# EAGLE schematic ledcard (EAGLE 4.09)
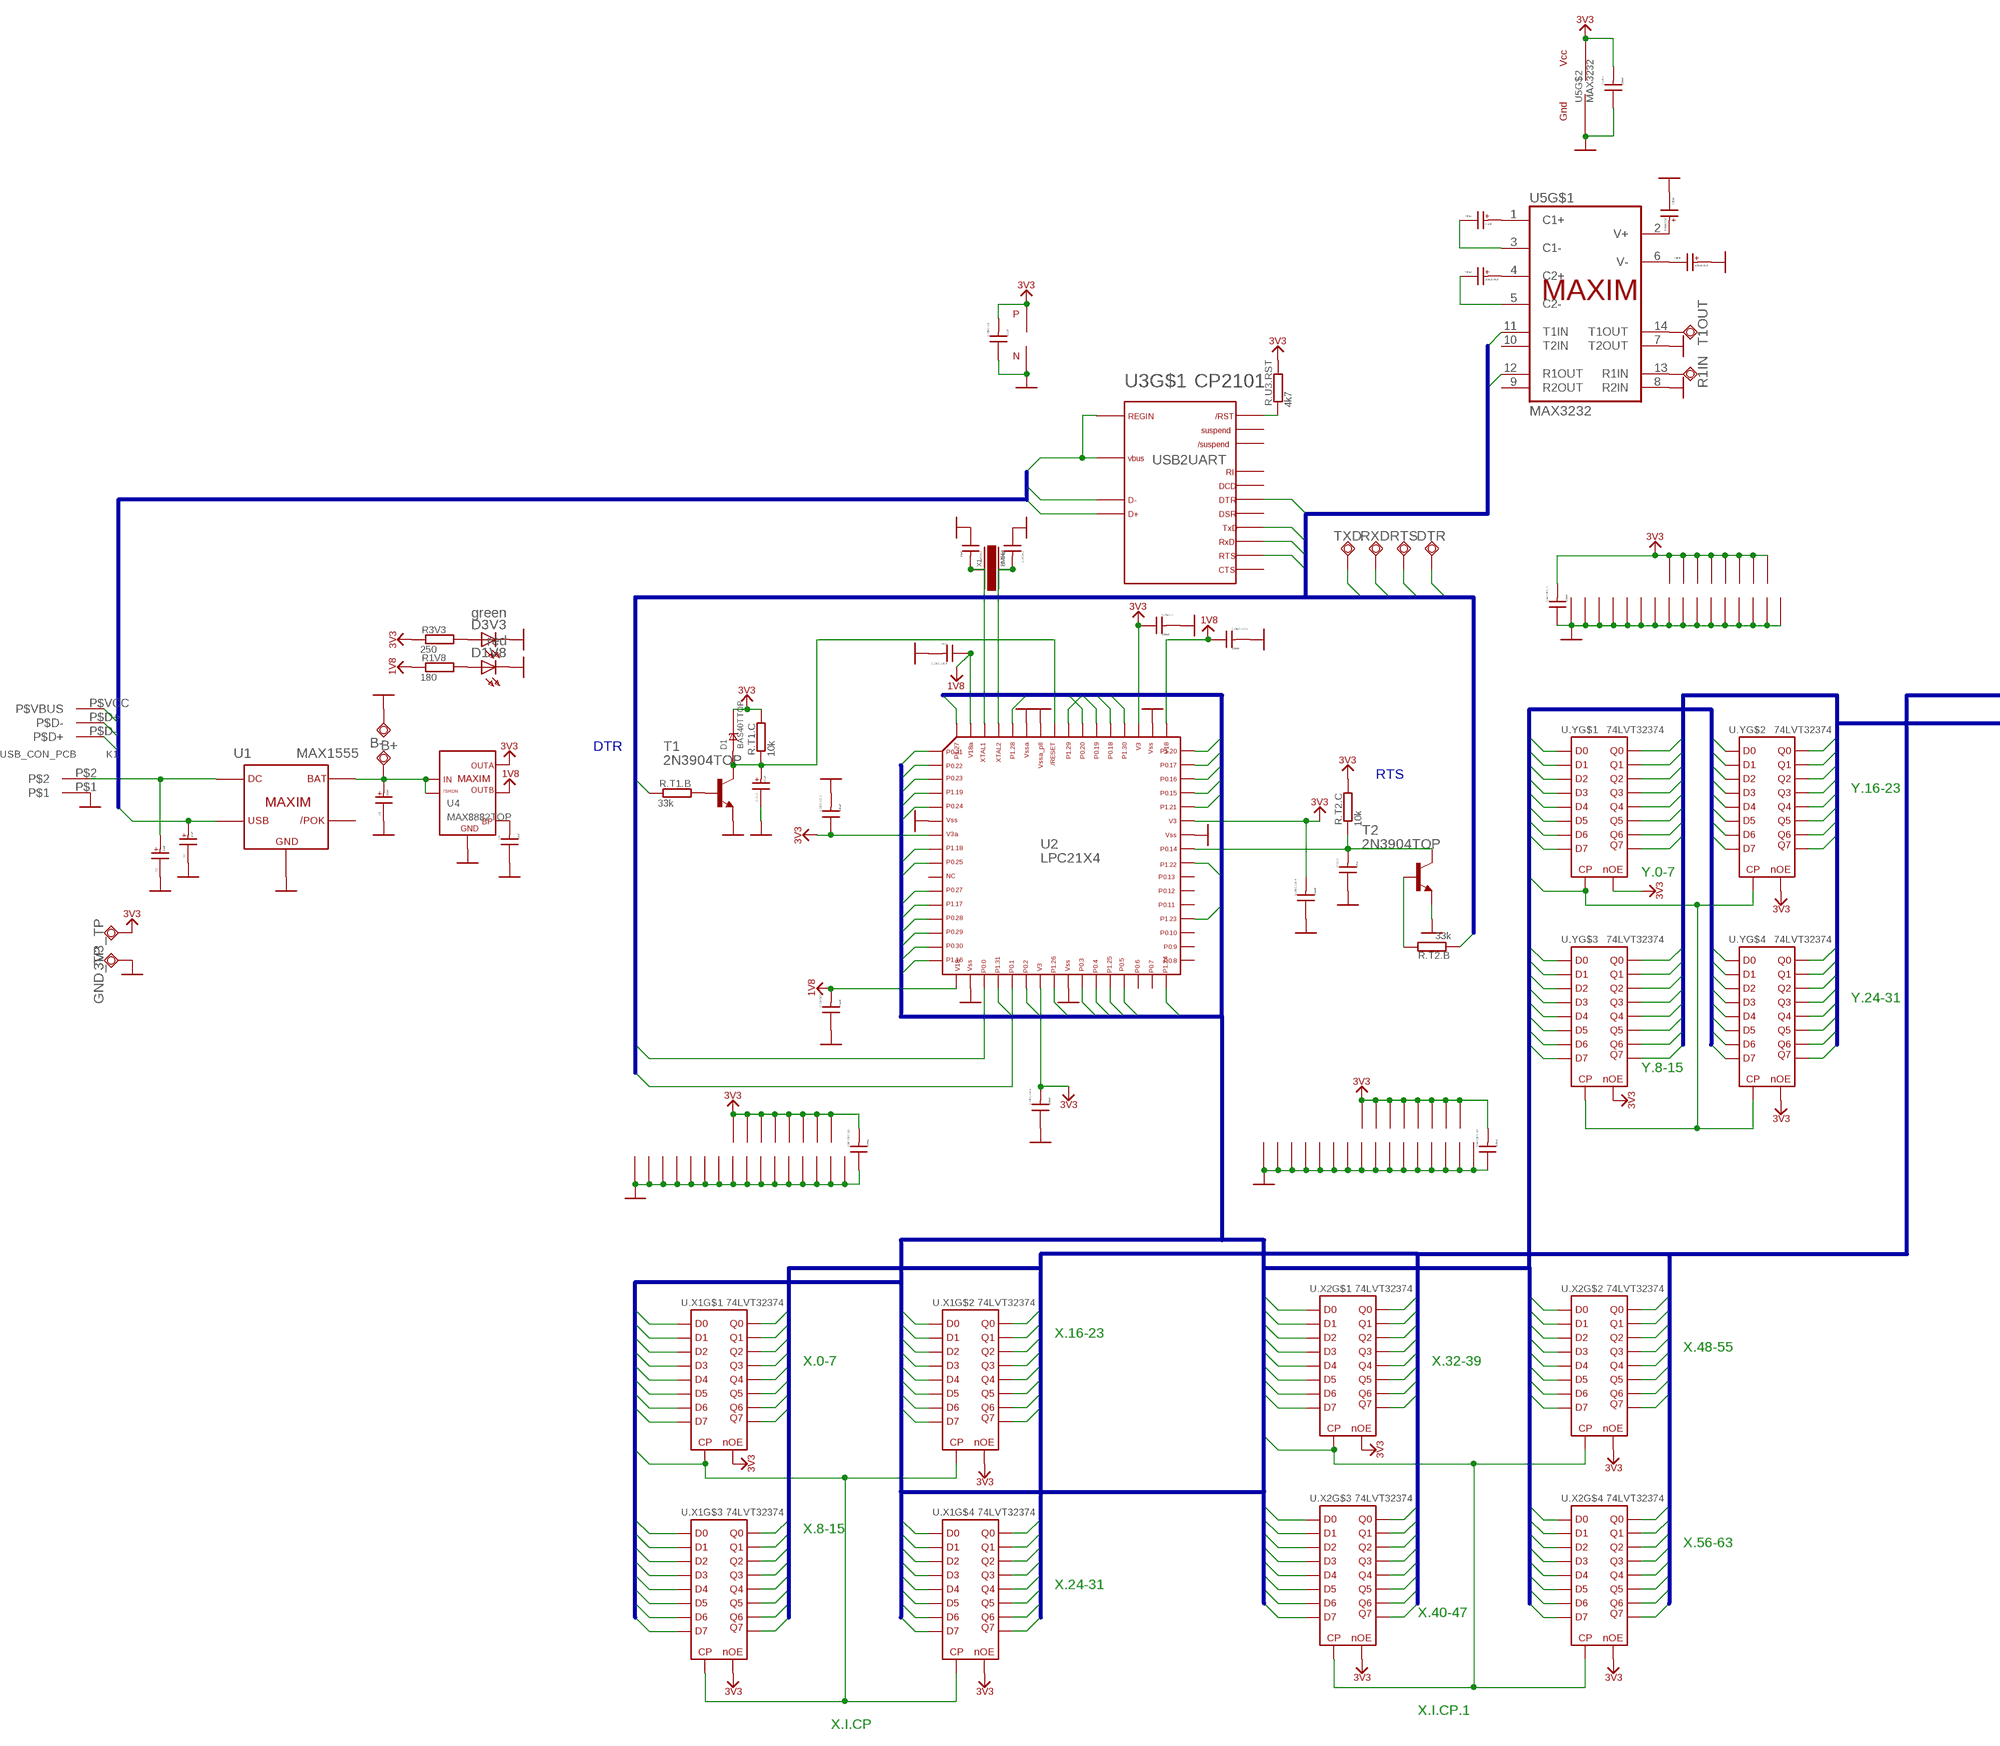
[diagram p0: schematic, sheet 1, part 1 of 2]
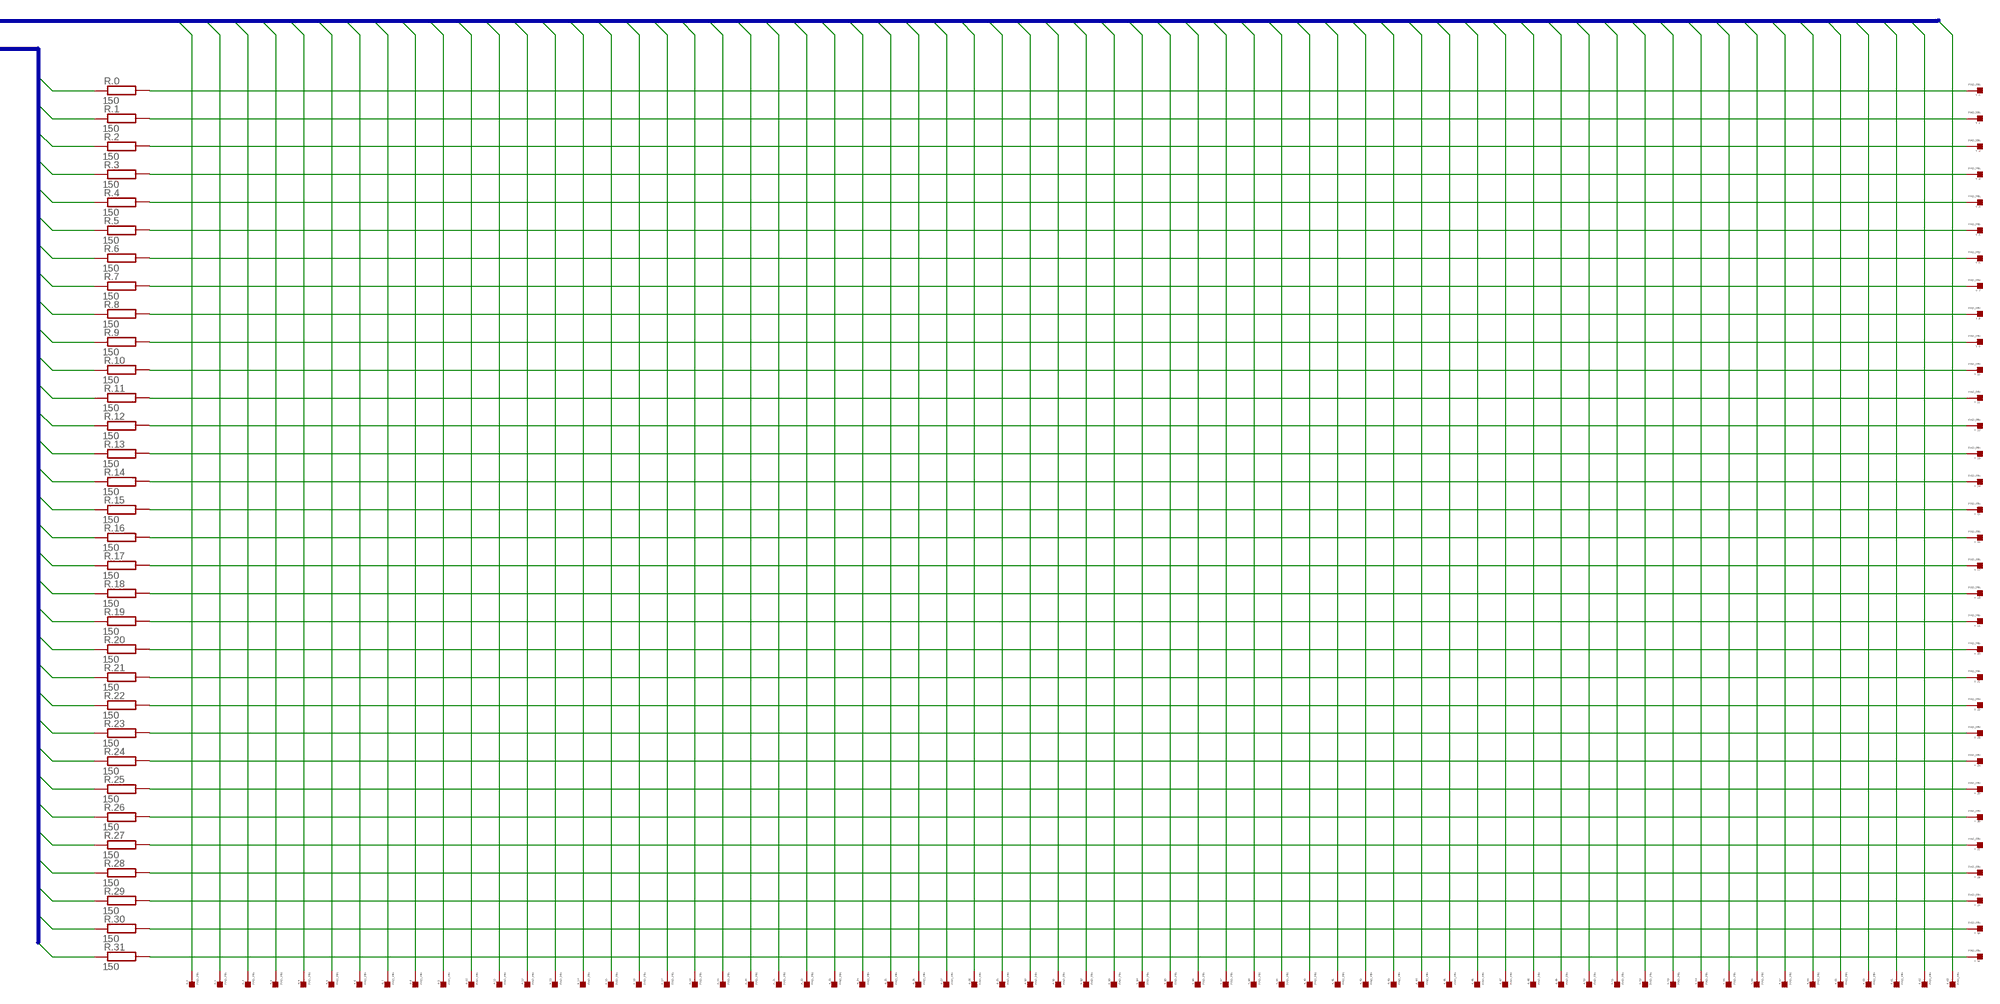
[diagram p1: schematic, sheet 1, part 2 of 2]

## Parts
3V3_TP  B2,54  [B2,54]
B+  B2,54  [B2,54]
B-  B2,54  [B2,54]
C1  10uF  CAP_A  [CAP_A]
C2  10uF  CAP_A  [CAP_A]
C3  10uF  CAP_A  [CAP_A]
C4  10uF  CAP_CERAMIC  [CAP_CERAMIC]
C.DEC.1  100nF  CAP_CERAMIC  [CAP_CERAMIC]
C.DEC.U2.1  100nF  CAP_CERAMIC  [CAP_CERAMIC]
C.DEC.U2.3  100nF  CAP_CERAMIC  [CAP_CERAMIC]
C.DEC.U2.5  100nF  CAP_CERAMIC  [CAP_CERAMIC]
C.DEC.U2.6  100n  CAP_CERAMIC  [CAP_CERAMIC]
C.DEC.U3  0.1uF  CAP_CERAMIC  [CAP_CERAMIC]
C.T1.C  10uF  CAP_A  [CAP_A]
C.T2.C  100n  CAP_CERAMIC  [CAP_CERAMIC]
C.U2.DEC.2  100nF  CAP_CERAMIC  [CAP_CERAMIC]
C.U5.1  100nF  CAP_CERAMIC  [CAP_CERAMIC]
C.XTAL1  22pF  CAP_CERAMIC  [CAP_CERAMIC]
C.XTAL2  22pF  CAP_CERAMIC  [CAP_CERAMIC]
CAP.DEC.X1  100Nf  CAP_CERAMIC  [CAP_CERAMIC]
CAP.DEC.X2  100nF  CAP_CERAMIC  [CAP_CERAMIC]
CAP.DEC.Y  100nF  CAP_CERAMIC  [CAP_CERAMIC]
D1  BAS40TTOP  [SOT23]
D1V8  red  LED0603_TOP  [LED_0603]
D3V3  green  LED0603_TOP  [LED_0603]
D.DEC.U2.4  100nF  CAP_CERAMIC  [CAP_CERAMIC]
DTR  B2,54  [B2,54]
GND_TP  B2,54  [B2,54]
K1  USB_CON_PCB  [USB_CON]
R1IN  B2,54  [B2,54]
R1V8  180  SMD_R  [SMDR]
R3V3  250  SMD_R  [SMDR]
R.0  150  SMD_R  [SMDR]
R.1  150  SMD_R  [SMDR]
R.2  150  SMD_R  [SMDR]
R.3  150  SMD_R  [SMDR]
R.4  150  SMD_R  [SMDR]
R.5  150  SMD_R  [SMDR]
R.6  150  SMD_R  [SMDR]
R.7  150  SMD_R  [SMDR]
R.8  150  SMD_R  [SMDR]
R.9  150  SMD_R  [SMDR]
R.10  150  SMD_R  [SMDR]
R.11  150  SMD_R  [SMDR]
R.12  150  SMD_R  [SMDR]
R.13  150  SMD_R  [SMDR]
R.14  150  SMD_R  [SMDR]
R.15  150  SMD_R  [SMDR]
R.16  150  SMD_R  [SMDR]
R.17  150  SMD_R  [SMDR]
R.18  150  SMD_R  [SMDR]
R.19  150  SMD_R  [SMDR]
R.20  150  SMD_R  [SMDR]
R.21  150  SMD_R  [SMDR]
R.22  150  SMD_R  [SMDR]
R.23  150  SMD_R  [SMDR]
R.24  150  SMD_R  [SMDR]
R.25  150  SMD_R  [SMDR]
R.26  150  SMD_R  [SMDR]
R.27  150  SMD_R  [SMDR]
R.28  150  SMD_R  [SMDR]
R.29  150  SMD_R  [SMDR]
R.30  150  SMD_R  [SMDR]
R.31  150  SMD_R  [SMDR]
R.T1.B  33k  SMD_R  [SMDR]
R.T1.C  10k  SMD_R  [SMDR]
R.T2.B  33k  SMD_R  [SMDR]
R.T2.C  10k  SMD_R  [SMDR]
R.U3.RST  4k7  SMD_R  [SMDR]
RTS  B2,54  [B2,54]
RXD  B2,54  [B2,54]
T1  2N3904TOP  [SOT23]
T1OUT  B2,54  [B2,54]
T2  2N3904TOP  [SOT23]
TXD  B2,54  [B2,54]
U1  MAX1555  [SOT23-5]
U2  LPC21X4  [TQFP64]
U3  CP2101  [MLP-28]
U4  MAX8882TOP  [SOT-23_RT6]
U5  MAX3232  [TSOP16]
U$3  PIN2  [PIN2]
U$31  0.1uF  CAP_A  [CAP_A]
U$32  470nF/TNT  CAP_A  [CAP_A]
U$33  470nF/TNT  CAP_A  [CAP_A]
U$36  470nF/TNT  CAP_A  [CAP_A]
U.X1  74LVT32374  [LFBGA96]
U.X2  74LVT32374  [LFBGA96]
U.Y  74LVT32374  [LFBGA96]
X1  8MHz  XTAL  [XTAL]
X.0  PAD_PIN  [PAD0.012]
X.1  PAD_PIN  [PAD0.012]
X.2  PAD_PIN  [PAD0.012]
X.3  PAD_PIN  [PAD0.012]
X.4  PAD_PIN  [PAD0.012]
X.5  PAD_PIN  [PAD0.012]
X.6  PAD_PIN  [PAD0.012]
X.7  PAD_PIN  [PAD0.012]
X.8  PAD_PIN  [PAD0.012]
X.9  PAD_PIN  [PAD0.012]
X.10  PAD_PIN  [PAD0.012]
X.11  PAD_PIN  [PAD0.012]
X.12  PAD_PIN  [PAD0.012]
X.13  PAD_PIN  [PAD0.012]
X.14  PAD_PIN  [PAD0.012]
X.15  PAD_PIN  [PAD0.012]
X.16  PAD_PIN  [PAD0.012]
X.17  PAD_PIN  [PAD0.012]
X.18  PAD_PIN  [PAD0.012]
X.19  PAD_PIN  [PAD0.012]
X.20  PAD_PIN  [PAD0.012]
X.21  PAD_PIN  [PAD0.012]
X.22  PAD_PIN  [PAD0.012]
X.23  PAD_PIN  [PAD0.012]
X.24  PAD_PIN  [PAD0.012]
X.25  PAD_PIN  [PAD0.012]
X.26  PAD_PIN  [PAD0.012]
X.27  PAD_PIN  [PAD0.012]
X.28  PAD_PIN  [PAD0.012]
X.29  PAD_PIN  [PAD0.012]
X.30  PAD_PIN  [PAD0.012]
X.31  PAD_PIN  [PAD0.012]
X.32  PAD_PIN  [PAD0.012]
X.33  PAD_PIN  [PAD0.012]
X.34  PAD_PIN  [PAD0.012]
X.35  PAD_PIN  [PAD0.012]
X.36  PAD_PIN  [PAD0.012]
X.37  PAD_PIN  [PAD0.012]
X.38  PAD_PIN  [PAD0.012]
X.39  PAD_PIN  [PAD0.012]
X.40  PAD_PIN  [PAD0.012]
X.41  PAD_PIN  [PAD0.012]
X.42  PAD_PIN  [PAD0.012]
X.43  PAD_PIN  [PAD0.012]
X.44  PAD_PIN  [PAD0.012]
X.45  PAD_PIN  [PAD0.012]
X.46  PAD_PIN  [PAD0.012]
X.47  PAD_PIN  [PAD0.012]
X.48  PAD_PIN  [PAD0.012]
X.49  PAD_PIN  [PAD0.012]
X.50  PAD_PIN  [PAD0.012]
X.51  PAD_PIN  [PAD0.012]
X.52  PAD_PIN  [PAD0.012]
X.53  PAD_PIN  [PAD0.012]
X.54  PAD_PIN  [PAD0.012]
X.55  PAD_PIN  [PAD0.012]
X.56  PAD_PIN  [PAD0.012]
X.57  PAD_PIN  [PAD0.012]
X.58  PAD_PIN  [PAD0.012]
X.59  PAD_PIN  [PAD0.012]
X.60  PAD_PIN  [PAD0.012]
X.61  PAD_PIN  [PAD0.012]
X.62  PAD_PIN  [PAD0.012]
X.63  PAD_PIN  [PAD0.012]
Y.0  PAD_PIN  [PAD0.012]
Y.1  PAD_PIN  [PAD0.012]
Y.2  PAD_PIN  [PAD0.012]
Y.3  PAD_PIN  [PAD0.012]
Y.4  PAD_PIN  [PAD0.012]
Y.5  PAD_PIN  [PAD0.012]
Y.6  PAD_PIN  [PAD0.012]
Y.7  PAD_PIN  [PAD0.012]
Y.8  PAD_PIN  [PAD0.012]
Y.9  PAD_PIN  [PAD0.012]
Y.10  PAD_PIN  [PAD0.012]
Y.11  PAD_PIN  [PAD0.012]
Y.12  PAD_PIN  [PAD0.012]
Y.13  PAD_PIN  [PAD0.012]
Y.14  PAD_PIN  [PAD0.012]
Y.15  PAD_PIN  [PAD0.012]
Y.16  PAD_PIN  [PAD0.012]
Y.17  PAD_PIN  [PAD0.012]
Y.18  PAD_PIN  [PAD0.012]
Y.19  PAD_PIN  [PAD0.012]
Y.20  PAD_PIN  [PAD0.012]
Y.21  PAD_PIN  [PAD0.012]
Y.22  PAD_PIN  [PAD0.012]
Y.23  PAD_PIN  [PAD0.012]
Y.24  PAD_PIN  [PAD0.012]
Y.25  PAD_PIN  [PAD0.012]
Y.26  PAD_PIN  [PAD0.012]
Y.27  PAD_PIN  [PAD0.012]
Y.28  PAD_PIN  [PAD0.012]
Y.29  PAD_PIN  [PAD0.012]
Y.30  PAD_PIN  [PAD0.012]
Y.31  PAD_PIN  [PAD0.012]

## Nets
1V8: C.DEC.U2.5.P$1 C.DEC.U2.6.P$1 C.U2.DEC.2.P$2 R1V8.P$1 U2.17 U2.49 U2.63 U4.1(P$OUT_B_1)
3V3: 3V3_TP.PP C.DEC.1.P$1 C.DEC.U2.1.P$1 C.DEC.U2.3.P$2 C.DEC.U3.P$2 C.U5.1.P$2 CAP.DEC.X1.P$2 CAP.DEC.X2.P$2 CAP.DEC.Y.P$2 D1.3(K) D.DEC.U2.4.P$2 R3V3.P$1 R.T1.C.P$2 R.T2.C.P$2 R.U3.RST.P$2 U2.7 U2.23 U2.43 U2.51 U3.P$6(P$P) U4.6(P$OUT_A_6) U5.16(VCC) U.X1.P$A3(P$NOE) U.X1.P$C3 U.X1.P$C4 U.X1.P$F3 U.X1.P$F4 U.X1.P$H3(P$NOE) U.X1.P$J3(P$NOE) U.X1.P$L3 U.X1.P$L4 U.X1.P$P3 U.X1.P$P4 U.X1.P$T3(P$NOE) U.X2.P$A3(P$NOE) U.X2.P$C3 U.X2.P$C4 U.X2.P$F3 U.X2.P$F4 U.X2.P$H3(P$NOE) U.X2.P$J3(P$NOE) U.X2.P$L3 U.X2.P$L4 U.X2.P$P3 U.X2.P$P4 U.X2.P$T3(P$NOE) U.Y.P$A3(P$NOE) U.Y.P$C3 U.Y.P$C4 U.Y.P$F3 U.Y.P$F4 U.Y.P$H3(P$NOE) U.Y.P$J3(P$NOE) U.Y.P$L3 U.Y.P$L4 U.Y.P$P3 U.Y.P$P4 U.Y.P$T3(P$NOE)
B$COM.DTR: DTR.PP R.T1.B.P$1 U3.P$28(P$DTR)
B$COM.RTS: R.T2.B.P$1 RTS.PP U3.P$9(P$RTS)
B$COM.RXD: RXD.PP U2.21 U3.P$25(P$RXD) U5.12(R1OUT)
B$COM.TXD: TXD.PP U2.19 U3.P$26(P$TXD) U5.11(T1IN)
B$I.0: U2.45 U.X1.P$A5(P$D0) U.X2.P$A5(P$D0) U.Y.P$A5(P$D0)
B$I.1: U2.46 U.X1.P$A6(P$D1) U.X2.P$A6(P$D1) U.Y.P$A6(P$D1)
B$I.2: U2.47 U.X1.P$B5(P$D2) U.X2.P$B5(P$D2) U.Y.P$B5(P$D2)
B$I.3: U2.53 U.X1.P$B6(P$D3) U.X2.P$B6(P$D3) U.Y.P$B6(P$D3)
B$I.4: U2.54 U.X1.P$C5(P$D4) U.X2.P$C5(P$D4) U.Y.P$C5(P$D4)
B$I.5: U2.55 U.X1.P$C6(P$D5) U.X2.P$C6(P$D5) U.Y.P$C6(P$D5)
B$I.6: U2.1 U.X1.P$D5(P$D6) U.X2.P$D5(P$D6) U.Y.P$D5(P$D6)
B$I.7: U2.2 U.X1.P$D6(P$D7) U.X2.P$D6(P$D7) U.Y.P$D6(P$D7)
B$I.8: U2.3 U.X1.P$J5(P$D0) U.X2.P$J5(P$D0) U.Y.P$J5(P$D0)
B$I.9: U2.5 U.X1.P$J6(P$D1) U.X2.P$J6(P$D1) U.Y.P$J6(P$D1)
B$I.10: U2.9 U.X1.P$K5(P$D2) U.X2.P$K5(P$D2) U.Y.P$K5(P$D2)
B$I.11: U2.29 U.X1.P$K6(P$D3) U.X2.P$K6(P$D3) U.Y.P$K6(P$D3)
B$I.12: U2.11 U.X1.P$L5(P$D4) U.X2.P$L5(P$D4) U.Y.P$L5(P$D4)
B$I.13: U2.13 U.X1.P$L6(P$D5) U.X2.P$L6(P$D5) U.Y.P$L6(P$D5)
B$I.14: U2.14 U.X1.P$M5(P$D6) U.X2.P$M5(P$D6) U.Y.P$M5(P$D6)
B$I.15: U2.15 U.X1.P$M6(P$D7) U.X2.P$M6(P$D7) U.Y.P$M6(P$D7)
B$I.16: U2.16 U.X1.P$E5(P$D0) U.X2.P$E5(P$D0) U.Y.P$E5(P$D0)
B$I.17: U2.12 U.X1.P$E6(P$D1) U.X2.P$E6(P$D1) U.Y.P$E6(P$D1)
B$I.18: U2.8 U.X1.P$F5(P$D2) U.X2.P$F5(P$D2) U.Y.P$F5(P$D2)
B$I.19: U2.4 U.X1.P$F6(P$D3) U.X2.P$F6(P$D3) U.Y.P$F6(P$D3)
B$I.20: U2.48 U.X1.P$G5(P$D4) U.X2.P$G5(P$D4) U.Y.P$G5(P$D4)
B$I.21: U2.44 U.X1.P$G6(P$D5) U.X2.P$G6(P$D5) U.Y.P$G6(P$D5)
B$I.22: U2.40 U.X1.P$H6(P$D6) U.X2.P$H6(P$D6) U.Y.P$H6(P$D6)
B$I.23: U2.36 U.X1.P$H5(P$D7) U.X2.P$H5(P$D7) U.Y.P$H5(P$D7)
B$I.24: U2.32 U.X1.P$N5(P$D0) U.X2.P$N5(P$D0) U.Y.P$N5(P$D0)
B$I.25: U2.28 U.X1.P$N6(P$D1) U.X2.P$N6(P$D1) U.Y.P$N6(P$D1)
B$I.26: U2.24 U.X1.P$P5(P$D2) U.X2.P$P5(P$D2) U.Y.P$P5(P$D2)
B$I.27: U2.64 U.X1.P$P6(P$D3) U.X2.P$P6(P$D3) U.Y.P$P6(P$D3)
B$I.28: U2.60 U.X1.P$R5(P$D4) U.X2.P$R5(P$D4) U.Y.P$R5(P$D4)
B$I.29: U2.56 U.X1.P$R6(P$D5) U.X2.P$R6(P$D5) U.Y.P$R6(P$D5)
B$I.30: U2.52 U.X1.P$T6(P$D6) U.X2.P$T6(P$D6) U.Y.P$T6(P$D6)
B$I.31: U2.20 U.X1.P$T5(P$D7) U.X2.P$T5(P$D7) U.Y.P$T5(P$D7)
B$USB.D+: K1.P$D-(P$D+) U3.P$4(P$D+)
B$USB.D-: K1.P$D+(P$D-) U3.P$5(P$D-)
B$USB.VBUS: C2.P K1.P$VCC(P$VBUS) U1.1(P$USB) U3.P$7(P$REGIN) U3.P$8(P$VBUS)
B$X.I.CP: U2.22 U.X1.P$A4(P$CP) U.X1.P$H4(P$CP) U.X1.P$J4(P$CP) U.X1.P$T4(P$CP)
B$X.I.CP.1: U2.26 U.X2.P$A4(P$CP) U.X2.P$H4(P$CP) U.X2.P$J4(P$CP) U.X2.P$T4(P$CP)
B$X.O.0: U.X1.P$A2(P$Q0) X.0.P$
B$X.O.1: U.X1.P$A1(P$Q1) X.1.P$
B$X.O.2: U.X1.P$B2(P$Q2) X.2.P$
B$X.O.3: U.X1.P$B1(P$Q3) X.3.P$
B$X.O.4: U.X1.P$C2(P$Q4) X.4.P$
B$X.O.5: U.X1.P$C1(P$Q5) X.5.P$
B$X.O.6: U.X1.P$D2(P$Q6) X.6.P$
B$X.O.7: U.X1.P$D1(P$Q7) X.7.P$
B$X.O.8: U.X1.P$J2(P$Q0) X.8.P$
B$X.O.9: U.X1.P$J1(P$Q1) X.9.P$
B$X.O.10: U.X1.P$K2(P$Q2) X.10.P$
B$X.O.11: U.X1.P$K1(P$Q3) X.11.P$
B$X.O.12: U.X1.P$L2(P$Q4) X.12.P$
B$X.O.13: U.X1.P$L1(P$Q5) X.13.P$
B$X.O.14: U.X1.P$M2(P$Q6) X.14.P$
B$X.O.15: U.X1.P$M1(P$Q7) X.15.P$
B$X.O.16: U.X1.P$E2(P$Q0) X.16.P$
B$X.O.17: U.X1.P$E1(P$Q1) X.17.P$
B$X.O.18: U.X1.P$F2(P$Q2) X.18.P$
B$X.O.19: U.X1.P$F1(P$Q3) X.19.P$
B$X.O.20: U.X1.P$G2(P$Q4) X.20.P$
B$X.O.21: U.X1.P$G1(P$Q5) X.21.P$
B$X.O.22: U.X1.P$H1(P$Q6) X.22.P$
B$X.O.23: U.X1.P$H2(P$Q7) X.23.P$
B$X.O.24: U.X1.P$N2(P$Q0) X.24.P$
B$X.O.25: U.X1.P$N1(P$Q1) X.25.P$
B$X.O.26: U.X1.P$P2(P$Q2) X.26.P$
B$X.O.27: U.X1.P$P1(P$Q3) X.27.P$
B$X.O.28: U.X1.P$R2(P$Q4) X.28.P$
B$X.O.29: U.X1.P$R1(P$Q5) X.29.P$
B$X.O.30: U.X1.P$T1(P$Q6) X.30.P$
B$X.O.31: U.X1.P$T2(P$Q7) X.31.P$
B$X.O.32: U.X2.P$A2(P$Q0) X.32.P$
B$X.O.33: U.X2.P$A1(P$Q1) X.33.P$
B$X.O.34: U.X2.P$B2(P$Q2) X.34.P$
B$X.O.35: U.X2.P$B1(P$Q3) X.35.P$
B$X.O.36: U.X2.P$C2(P$Q4) X.36.P$
B$X.O.37: U.X2.P$C1(P$Q5) X.37.P$
B$X.O.38: U.X2.P$D2(P$Q6) X.38.P$
B$X.O.39: U.X2.P$D1(P$Q7) X.39.P$
B$X.O.40: U.X2.P$J2(P$Q0) X.40.P$
B$X.O.41: U.X2.P$J1(P$Q1) X.41.P$
B$X.O.42: U.X2.P$K2(P$Q2) X.42.P$
B$X.O.43: U.X2.P$K1(P$Q3) X.43.P$
B$X.O.44: U.X2.P$L2(P$Q4) X.44.P$
B$X.O.45: U.X2.P$L1(P$Q5) X.45.P$
B$X.O.46: U.X2.P$M2(P$Q6) X.46.P$
B$X.O.47: U.X2.P$M1(P$Q7) X.47.P$
B$X.O.48: U.X2.P$E2(P$Q0) X.48.P$
B$X.O.49: U.X2.P$E1(P$Q1) X.49.P$
B$X.O.50: U.X2.P$F2(P$Q2) X.50.P$
B$X.O.51: U.X2.P$F1(P$Q3) X.51.P$
B$X.O.52: U.X2.P$G2(P$Q4) X.52.P$
B$X.O.53: U.X2.P$G1(P$Q5) X.53.P$
B$X.O.54: U.X2.P$H1(P$Q6) X.54.P$
B$X.O.55: U.X2.P$H2(P$Q7) X.55.P$
B$X.O.56: U.X2.P$N2(P$Q0) X.56.P$
B$X.O.57: U.X2.P$N1(P$Q1) X.57.P$
B$X.O.58: U.X2.P$P2(P$Q2) X.58.P$
B$X.O.59: U.X2.P$P1(P$Q3) X.59.P$
B$X.O.60: U.X2.P$R2(P$Q4) X.60.P$
B$X.O.61: U.X2.P$R1(P$Q5) X.61.P$
B$X.O.62: U.X2.P$T1(P$Q6) X.62.P$
B$X.O.63: U.X2.P$T2(P$Q7) X.63.P$
B$Y.I.CP: U2.27 U.Y.P$A4(P$CP) U.Y.P$H4(P$CP) U.Y.P$J4(P$CP) U.Y.P$T4(P$CP)
B$Y.O.0: R.0.P$1 U.Y.P$A2(P$Q0)
B$Y.O.1: R.1.P$1 U.Y.P$A1(P$Q1)
B$Y.O.2: R.2.P$1 U.Y.P$B2(P$Q2)
B$Y.O.3: R.3.P$1 U.Y.P$B1(P$Q3)
B$Y.O.4: R.4.P$1 U.Y.P$C2(P$Q4)
B$Y.O.5: R.5.P$1 U.Y.P$C1(P$Q5)
B$Y.O.6: R.6.P$1 U.Y.P$D2(P$Q6)
B$Y.O.7: R.7.P$1 U.Y.P$D1(P$Q7)
B$Y.O.8: R.8.P$1 U.Y.P$J2(P$Q0)
B$Y.O.9: R.9.P$1 U.Y.P$J1(P$Q1)
B$Y.O.10: R.10.P$1 U.Y.P$K2(P$Q2)
B$Y.O.11: R.11.P$1 U.Y.P$K1(P$Q3)
B$Y.O.12: R.12.P$1 U.Y.P$L2(P$Q4)
B$Y.O.13: R.13.P$1 U.Y.P$L1(P$Q5)
B$Y.O.14: R.14.P$1 U.Y.P$M2(P$Q6)
B$Y.O.15: R.15.P$1 U.Y.P$M1(P$Q7)
B$Y.O.16: R.16.P$1 U.Y.P$E2(P$Q0)
B$Y.O.17: R.17.P$1 U.Y.P$E1(P$Q1)
B$Y.O.18: R.18.P$1 U.Y.P$F2(P$Q2)
B$Y.O.19: R.19.P$1 U.Y.P$F1(P$Q3)
B$Y.O.20: R.20.P$1 U.Y.P$G2(P$Q4)
B$Y.O.21: R.21.P$1 U.Y.P$G1(P$Q5)
B$Y.O.22: R.22.P$1 U.Y.P$H1(P$Q6)
B$Y.O.23: R.23.P$1 U.Y.P$H2(P$Q7)
B$Y.O.24: R.24.P$1 U.Y.P$N2(P$Q0)
B$Y.O.25: R.25.P$1 U.Y.P$N1(P$Q1)
B$Y.O.26: R.26.P$1 U.Y.P$P2(P$Q2)
B$Y.O.27: R.27.P$1 U.Y.P$P1(P$Q3)
B$Y.O.28: R.28.P$1 U.Y.P$R2(P$Q4)
B$Y.O.29: R.29.P$1 U.Y.P$R1(P$Q5)
B$Y.O.30: R.30.P$1 U.Y.P$T1(P$Q6)
B$Y.O.31: R.31.P$1 U.Y.P$T2(P$Q7)
GND: B-.PP C1.N C2.N C3.N C4.P$1 C.DEC.1.P$2 C.DEC.U2.1.P$2 C.DEC.U2.3.P$1 C.DEC.U2.5.P$2 C.DEC.U2.6.P$2 C.DEC.U3.P$1 C.T1.C.N C.T2.C.P$1 C.U2.DEC.2.P$1 C.U5.1.P$1 C.XTAL1.P$1 C.XTAL2.P$1 CAP.DEC.X1.P$1 CAP.DEC.X2.P$1 CAP.DEC.Y.P$1 D1V8.P$K(C) D3V3.P$K(C) D.DEC.U2.4.P$1 GND_TP.PP T1.2(E) T2.2(E) U1.2(P$GND) U2.6 U2.18 U2.25 U2.42 U2.50 U2.58 U2.59 U3.P$3(P$N) U4.2(P$GND_2) U5.7(T2OUT) U5.8(R2IN) U5.15(GND) U$3.P$1 U$33.N U$36.P U.X1.P$B3 U.X1.P$B4 U.X1.P$D3 U.X1.P$D4 U.X1.P$E3 U.X1.P$E4 U.X1.P$G3 U.X1.P$G4 U.X1.P$K3 U.X1.P$K4 U.X1.P$M3 U.X1.P$M4 U.X1.P$N3 U.X1.P$N4 U.X1.P$R3 U.X1.P$R4 U.X2.P$B3 U.X2.P$B4 U.X2.P$D3 U.X2.P$D4 U.X2.P$E3 U.X2.P$E4 U.X2.P$G3 U.X2.P$G4 U.X2.P$K3 U.X2.P$K4 U.X2.P$M3 U.X2.P$M4 U.X2.P$N3 U.X2.P$N4 U.X2.P$R3 U.X2.P$R4 U.Y.P$B3 U.Y.P$B4 U.Y.P$D3 U.Y.P$D4 U.Y.P$E3 U.Y.P$E4 U.Y.P$G3 U.Y.P$G4 U.Y.P$K3 U.Y.P$K4 U.Y.P$M3 U.Y.P$M4 U.Y.P$N3 U.Y.P$N4 U.Y.P$R3 U.Y.P$R4
N$1: R.T1.B.P$2 T1.1(B)
N$2: B+.PP C3.P U1.5(P$BAT) U4.4(P$SHDN_4) U4.5(P$IN_5)
N$3: R.U3.RST.P$1 U3.P$24(P$RST)
N$4: C.XTAL1.P$2 U2.62 X1.P$1
N$5: C4.P$2 U4.3(P$BP_3)
N$6: C.XTAL2.P$2 U2.61 X1.P$2
N$7: D3V3.P$A(A) R3V3.P$2
N$8: D1V8.P$A(A) R1V8.P$2
N$9: U5.2(V+) U$33.P
N$10: U5.6(V-) U$36.N
N$11: C.T2.C.P$2 R.T2.C.P$1 T2.3(C) U2.41
N$12: C.T1.C.P D1.1(A) R.T1.C.P$1 T1.3(C) U2.57
N$13: R.T2.B.P$2 T2.1(B)
N$14: U5.1(C1+) U$31.P
N$15: U5.3(C1-) U$31.N
N$16: U5.4(C2+) U$32.P
N$17: U5.5(C2-) U$32.N
N$18: T1OUT.PP U5.14(T1OUT)
N$19: R1IN.PP U5.13(R1IN)
N$R.0: R.0.P$2 Y.0.P$
N$R.1: R.1.P$2 Y.1.P$
N$R.2: R.2.P$2 Y.2.P$
N$R.3: R.3.P$2 Y.3.P$
N$R.4: R.4.P$2 Y.4.P$
N$R.5: R.5.P$2 Y.5.P$
N$R.6: R.6.P$2 Y.6.P$
N$R.7: R.7.P$2 Y.7.P$
N$R.8: R.8.P$2 Y.8.P$
N$R.9: R.9.P$2 Y.9.P$
N$R.10: R.10.P$2 Y.10.P$
N$R.11: R.11.P$2 Y.11.P$
N$R.12: R.12.P$2 Y.12.P$
N$R.13: R.13.P$2 Y.13.P$
N$R.14: R.14.P$2 Y.14.P$
N$R.15: R.15.P$2 Y.15.P$
N$R.16: R.16.P$2 Y.16.P$
N$R.17: R.17.P$2 Y.17.P$
N$R.18: R.18.P$2 Y.18.P$
N$R.19: R.19.P$2 Y.19.P$
N$R.20: R.20.P$2 Y.20.P$
N$R.21: R.21.P$2 Y.21.P$
N$R.22: R.22.P$2 Y.22.P$
N$R.23: R.23.P$2 Y.23.P$
N$R.24: R.24.P$2 Y.24.P$
N$R.25: R.25.P$2 Y.25.P$
N$R.26: R.26.P$2 Y.26.P$
N$R.27: R.27.P$2 Y.27.P$
N$R.28: R.28.P$2 Y.28.P$
N$R.29: R.29.P$2 Y.29.P$
N$R.30: R.30.P$2 Y.30.P$
N$R.31: R.31.P$2 Y.31.P$
VCC: C1.P U1.4(P$DC) U$3.P$2
Unconnected: U1.3(P$/POK) U2.10 U2.30 U2.31 U2.33 U2.34 U2.35 U2.37 U2.38 U2.39 U3.P$1(P$DCD) U3.P$2(P$RI) U3.P$10(P$NC) U3.P$11(P$/SUSSPEND) U3.P$12(P$SUSSPEND) U3.P$13(P$NC) U3.P$14(P$NC) U3.P$15(P$NC) U3.P$16(P$NC) U3.P$17(P$NC) U3.P$18(P$NC) U3.P$19(P$NC) U3.P$20(P$NC) U3.P$21(P$NC) U3.P$22(P$NC) U3.P$23(P$CTS) U3.P$27(P$DSR) U5.9(R2OUT) U5.10(T2IN)

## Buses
B$COM
B$USB
B$X.O
B$I
B$Y.O

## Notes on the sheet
- DTR
- RTS
- Y.16-23
- Y.0-7
- Y.24-31
- Y.8-15
- X.16-23
- X.48-55
- X.0-7 | X.32-39
- X.8-15
- X.56-63
- X.24-31
- X.40-47
- X.I.CP.1
- X.I.CP

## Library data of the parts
3V3_TP B+ B- DTR GND_TP R1IN RTS RXD T1OUT TXD = testpad:B2,54: TEST PIN
C1-C3 C.T1.C U$31-U$33 U$36 = On_Track:CAP_A
C4 C.DEC.1 C.DEC.U2.1 C.DEC.U2.3 C.DEC.U2.5 C.DEC.U2.6 C.DEC.U3 C.T2.C C.U2.DEC.2 C.U5.1 C.XTAL1 C.XTAL2 CAP.DEC.X1 CAP.DEC.X2 CAP.DEC.Y D.DEC.U2.4 = On_Track:CAP_CERAMIC
D1 = On_Track:BAS40T
D1V8 D3V3 = On_Track:LED
K1 = Devs:USB_CON_PCB
R1V8 R3V3 R.0 R.1-R.31 R.T1.B R.T1.C R.T2.B R.T2.C R.U3.RST = On_Track:SMD_R
T1 T2 = On_Track:2N3904
U1 = Devs:MAX1555
U2 = On_Track:LPC21X4
U3 = Devs:CP2101
U4 = On_Track:MAX8882
U5 = On_Track:MAX3232
U$3 = Devs:PIN2
U.X1 U.X2 U.Y = Plastic:74LVT32374
X1 = On_Track:XTAL
X.0 X.1-X.63 Y.0 Y.1-Y.31 = Devs:PAD_PIN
